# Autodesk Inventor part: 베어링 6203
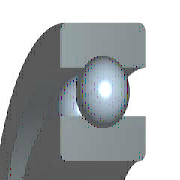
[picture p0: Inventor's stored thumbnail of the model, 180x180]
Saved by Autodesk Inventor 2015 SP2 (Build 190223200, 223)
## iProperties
IsCustomPart: 0
Company: 한국ATC센터
Created: 2014-10
Part Number: 베어링 6203
Material: 강철
Description: 깊은 그루브 볼 베어링
Document SubType Name: Modeling
Standard: KS B 2023
Designer: KYOUNG IL JANG
Standards Organization: KS
Language: ko-KR
Size Designation: 6203 - 17 x 40 x 12
Categories: <MemberInstance><Categories><Category DisplayName="샤프트 부품" InternalName="7f7aeb1f-a693-4053-b835-cee3144e0d98" Mnemonic="SHFT"><Category DisplayName="베어링" Inter
Density: 7.85 g/cm^3
Mass: 64.8982 g
Surface Area: 64.3582 cm^2
Volume: 8.26729 cm^3
Appearance: 강철 - 광택
Author: KYOUNG IL JANG
Revision Number: 1
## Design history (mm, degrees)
sketch "스케치" dims "d0" = 5.98 (= -0.26 x WD + 0.26 x BD)
  geometry: L1 (3.01, 14.25)-(8.99, 14.25); L2 (6, 14.25)-(6, 11.26); L3 (6, 14.25)-(6, 17.24); L4 (3.778, 12.249)-(0, 12.249); L5 (0, 8.5)-(12, 8.5); L6 (3.778, 16.251)-(0, 16.251); L7 (0, 20)-(12, 20); L8 (12, 8.5)-(12, 12.249); L9 (8.222, 12.249)-(12, 12.249); L10 (8.222, 16.251)-(12, 16.251); L11 (12, 20)-(12, 16.251); L12 (-1.4, 0)-(8.4, 0) reference; L13 (0, -0.3)-(0, 5.3) reference
  constraints: 22 end point, 4 point on line, 2 collinear, 2 perpendicular, 2 symmetric about line, 1 midpoint, 1 parallel, 14 other
  dimensions: "d9" = 17 diameter of L5 L12 (= WD); "d11" = 40 diameter of L7 L12 (= BD); "d12" = 12 distance between parallel lines of L8 L13 (= KB); "d13" = 24.498 diameter of L9 L12 (= 0.326 x BD + 0.674 x WD)
revolve "본체" stored, may be unused: angle "d6" = 90 deg
revolve "볼" stored, may be unused: angle "d7" = 90 deg
pattern_circular "IDS_ARRAYBALL[SIMPL:T]" dims angle "d3" = 360 deg
body "Solid1"
fillet "모깎기1" dims "d1" = 0.6 (= KRS)
other parameters: "WD" = 17 [user parameter; used in 5 equation terms], "BD" = 40 [user parameter; used in 5 equation terms], "KB" = 12 [user parameter; used in 1 equation term], "KRS" = 0.6 [user parameter; used in 1 equation term], "d4" = 0, "d5" = 0, "d8" = 0, "d14" = 0, "d15" = 0, "BBA" = 0 [user parameter], "BC0" = 4750000 [user parameter], "BC" = 9560000 [user parameter], "WR" = 8.5 (= 0.5 x WD) [user parameter]
